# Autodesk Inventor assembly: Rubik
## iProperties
Shininess: 64.0
Length Units: 11269
Angle Units: 11279
Time Units: 11290
Mass Units: 11283
Length Display Precision: 3
Angle Display Precision: 2
Compacted: True
Created: 2004-10
Part Number: Rubik
Document SubType Name: Assembly
Designer: W. Holzwarth
Manufacturer: Standard
Standards Organization: Custom
Density: 0.0
Volumn: 0.0
Area: 0.0
PropertySet Name: Model Information
Control State: 0
Master: False
Checked Out: False
Übersetzungsnorm: STEP AP214DIS
Dateiname: Rubik.STEP
Vorprozessor: SolidWorks 2003099
Postprozessor: Build: 081d, Release: 8 SP1 - Date: Tue 01/26/2004
Gesendete Einheiten: MILLIMETERS
Unbestimmtheit: 1e-05
Author: W. Holzwarth
